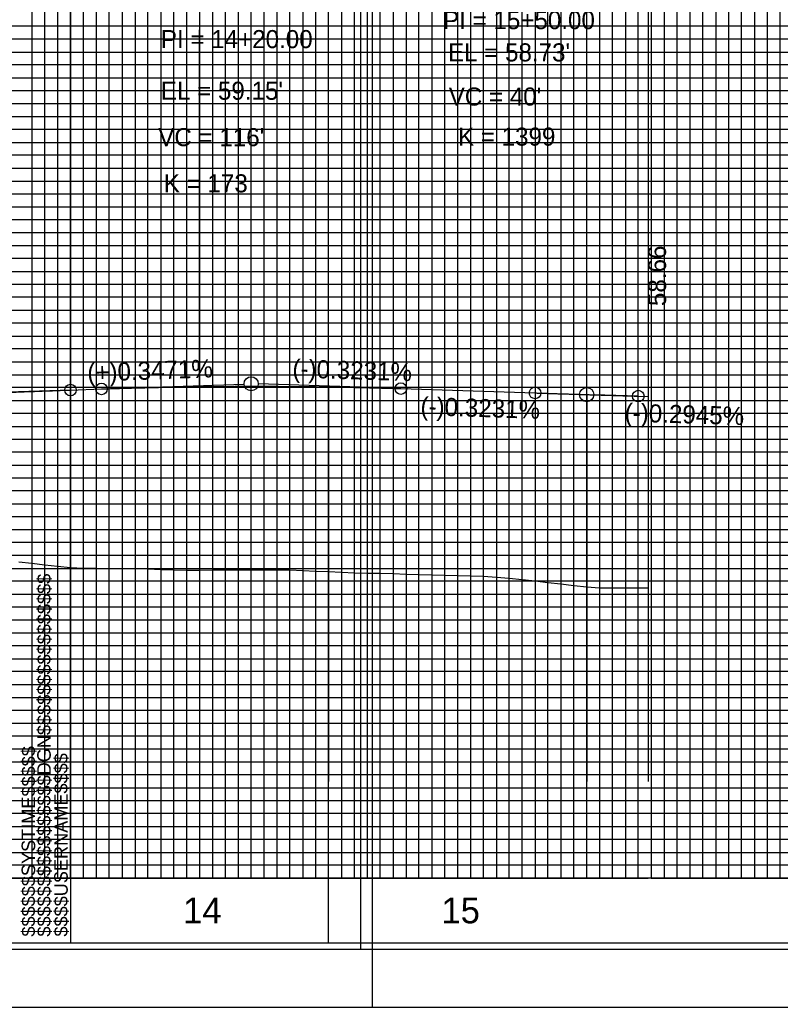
# Model space of a CAD drawing. Extents: x 2345490 to 2436403, y 465165 to 573888.
# Drawn here: x 2412225.7 to 2412520.3, y 518432.4 to 518814.9 of the extents above; entities that cross this region are included whole.
import ezdxf

# ---------------------------------------------------------------- set-up
doc = ezdxf.new("R2010")
doc.units = 0
for name, color, linetype in [('Old_Level_1', 7, 'Continuous'), ('Old_Level_18', 7, 'Continuous'), ('Old_Level_2', 7, 'Continuous'), ('Old_Level_40', 7, 'Continuous'), ('Old_Level_41', 7, 'Continuous'), ('Old_Level_42', 7, 'Continuous'), ('Old_Level_43', 7, 'Continuous'), ('Old_Level_50', 7, 'Continuous'), ('Old_Level_51', 7, 'Continuous'), ('Old_Level_63', 7, 'Continuous')]:
    doc.layers.add(name, color=color, linetype=linetype)

msp = doc.modelspace()

# ---------------------------------------------------------------- linework, layer by layer
at = {"layer": 'Old_Level_1'}
for points in [[(2412225.325, 518604.90725), (2412230.325, 518604.3525), (2412235.325, 518603.80575), (2412240.325, 518603.26725), (2412245.325, 518602.73625), (2412250.325, 518602.4955), (2412255.325, 518602.43975), (2412260.325, 518602.39125), (2412265.325, 518602.35), (2412270.325, 518602.31575), (2412275.325, 518602.22175), (2412280.325, 518601.9935), (2412285.325, 518601.77325), (2412290.325, 518601.71275), (2412295.325, 518601.756), (2412300.325, 518601.80375), (2412305.325, 518601.81125), (2412310.325, 518601.82475), (2412315.325, 518601.844), (2412320.325, 518601.8685), (2412325.325, 518601.89825), (2412330.325, 518601.77875), (2412335.325, 518601.56025), (2412340.325, 518601.346), (2412345.325, 518601.13575), (2412350.325, 518600.929), (2412355.325, 518600.726), (2412360.325, 518600.5605), (2412365.325, 518600.60725), (2412370.325, 518600.408), (2412375.325, 518600.09375), (2412380.325, 518599.97075), (2412385.325, 518599.84925), (2412390.325, 518599.72875), (2412395.325, 518599.60925)], [(2412395.325, 518599.60925), (2412400.325, 518599.49025), (2412405.325, 518599.3715), (2412410.325, 518599.056), (2412415.325, 518598.54475), (2412420.325, 518598.03325), (2412425.325, 518597.522), (2412430.325, 518596.94875), (2412435.325, 518596.36575), (2412440.325, 518595.78275), (2412445.325, 518595.19975), (2412450.325, 518594.8965), (2412455.325, 518594.9005), (2412460.325, 518594.8945), (2412465.325, 518594.88875), (2412469.095, 518594.88425)]]:
    msp.add_lwpolyline(points, dxfattribs=at)
at = {"layer": 'Old_Level_18'}
msp.add_line((2412245.325, 518457.40475), (2412245.325, 518457.40475), dxfattribs=at)
msp.add_line((2412245.325, 518457.40475), (2412245.325, 518457.40475), dxfattribs=at)
for points in [[(2412345.325, 519507.40475), (2410845.325, 519507.40475), (2410845.325, 518457.40475), (2412345.325, 518457.40475)], [(2413745.325, 519507.40475), (2412245.325, 519507.40475), (2412245.325, 518457.40475), (2413745.325, 518457.40475)]]:
    msp.add_lwpolyline(points, close=True, dxfattribs=at)
at = {"layer": 'Old_Level_2'}
for p, q in [((2412469.095, 518887.90475), (2412469.095, 518669.00475)), ((2412245.325, 518671.4755), (2412148.0735, 518668.10025)), ((2412245.325, 518671.4755), (2412257.325, 518671.892)), ((2412257.325, 518671.892), (2412312.57675, 518673.8095)), ((2412373.325, 518672.031), (2412318.07375, 518673.816)), ((2412373.325, 518672.031), (2412425.325, 518670.351)), ((2412425.325, 518670.351), (2412442.5765, 518669.79375)), ((2412465.325, 518669.116), (2412448.074, 518669.624)), ((2412465.325, 518669.116), (2412469.095, 518669.00475))]:
    msp.add_line(p, q, dxfattribs=at)
for centre, radius in [((2412257.325, 518671.892), 2.25), ((2412315.325, 518673.90475), 2.75), ((2412373.325, 518672.031), 2.25), ((2412245.325, 518671.4755), 2.25), ((2412425.325, 518670.351), 2.25), ((2412445.325, 518669.70475), 2.75), ((2412465.325, 518669.116), 2.25)]:
    msp.add_circle(centre, radius, dxfattribs=at)
for points in [[(2412045.325, 518659.12475), (2412049.325, 518659.478), (2412053.325, 518659.8265), (2412057.325, 518660.171), (2412061.325, 518660.511), (2412065.325, 518660.84675), (2412069.325, 518661.17825), (2412073.325, 518661.50525), (2412077.325, 518661.828), (2412081.325, 518662.1465), (2412085.325, 518662.4605), (2412089.325, 518662.77025), (2412093.325, 518663.07575), (2412097.325, 518663.37675), (2412101.325, 518663.6735), (2412105.325, 518663.966), (2412109.325, 518664.25425), (2412113.325, 518664.538), (2412117.325, 518664.8175), (2412121.325, 518665.0925), (2412125.325, 518665.36325), (2412129.325, 518665.62975), (2412133.325, 518665.892), (2412137.325, 518666.14975), (2412141.325, 518666.40325), (2412145.325, 518666.6525), (2412149.325, 518666.89725), (2412153.325, 518667.138), (2412157.325, 518667.374), (2412161.325, 518667.606), (2412165.325, 518667.8335), (2412169.325, 518668.05675), (2412173.325, 518668.2755), (2412177.325, 518668.49025), (2412181.325, 518668.70025), (2412185.325, 518668.90625), (2412189.325, 518669.10775), (2412193.325, 518669.305), (2412197.325, 518669.498), (2412201.325, 518669.6865), (2412205.325, 518669.87075), (2412209.325, 518670.05075), (2412213.325, 518670.2265), (2412217.325, 518670.39775), (2412221.325, 518670.56475), (2412225.325, 518670.72725), (2412229.325, 518670.8855), (2412233.325, 518671.0395), (2412237.325, 518671.18925), (2412241.325, 518671.3345), (2412245.325, 518671.4755)], [(2412257.325, 518671.892), (2412259.645, 518671.971), (2412261.965, 518672.04675), (2412264.285, 518672.1195), (2412266.605, 518672.18925), (2412268.925, 518672.25575), (2412271.245, 518672.319), (2412273.565, 518672.3795), (2412275.885, 518672.4365), (2412278.205, 518672.49075), (2412280.525, 518672.54175), (2412282.845, 518672.5895), (2412285.165, 518672.63425), (2412287.485, 518672.676), (2412289.805, 518672.7145), (2412292.125, 518672.75), (2412294.445, 518672.78225), (2412296.765, 518672.8115), (2412299.085, 518672.8375), (2412301.405, 518672.8605), (2412303.725, 518672.8805), (2412306.045, 518672.89725), (2412308.365, 518672.91075), (2412310.685, 518672.9215), (2412313.005, 518672.92875), (2412315.325, 518672.93325), (2412317.645, 518672.9345), (2412319.965, 518672.9325), (2412322.285, 518672.9275), (2412324.605, 518672.9195), (2412326.925, 518672.90825), (2412329.245, 518672.894), (2412331.565, 518672.8765), (2412333.885, 518672.856), (2412336.205, 518672.83225), (2412338.525, 518672.8055), (2412340.845, 518672.77575), (2412343.165, 518672.74275), (2412345.485, 518672.7065), (2412347.805, 518672.6675), (2412350.125, 518672.625), (2412352.445, 518672.57975), (2412354.765, 518672.53125), (2412357.085, 518672.4795), (2412359.405, 518672.42475), (2412361.725, 518672.367), (2412364.045, 518672.306), (2412366.365, 518672.242), (2412368.685, 518672.17475), (2412371.005, 518672.1045), (2412373.325, 518672.031)], [(2412425.325, 518670.351), (2412426.125, 518670.32525), (2412426.925, 518670.2995), (2412427.725, 518670.27375), (2412428.525, 518670.248), (2412429.325, 518670.22225), (2412430.125, 518670.19675), (2412430.925, 518670.17125), (2412431.725, 518670.14575), (2412432.525, 518670.12025), (2412433.325, 518670.09475), (2412434.125, 518670.0695), (2412434.925, 518670.04425), (2412435.725, 518670.019), (2412436.525, 518669.99375), (2412437.325, 518669.9685), (2412438.125, 518669.94325), (2412438.925, 518669.91825), (2412439.725, 518669.89325), (2412440.525, 518669.86825), (2412441.325, 518669.84325), (2412442.125, 518669.81825), (2412442.925, 518669.7935), (2412443.725, 518669.76875), (2412444.525, 518669.744), (2412445.325, 518669.71925), (2412446.125, 518669.6945), (2412446.925, 518669.66975), (2412447.725, 518669.64525), (2412448.525, 518669.62075), (2412449.325, 518669.59625), (2412450.125, 518669.57175), (2412450.925, 518669.54725), (2412451.725, 518669.523), (2412452.525, 518669.49875), (2412453.325, 518669.4745), (2412454.125, 518669.45025), (2412454.925, 518669.426), (2412455.725, 518669.402), (2412456.525, 518669.37775), (2412457.325, 518669.35375), (2412458.125, 518669.32975), (2412458.925, 518669.30575), (2412459.725, 518669.282), (2412460.525, 518669.258), (2412461.325, 518669.23425), (2412462.125, 518669.2105), (2412462.925, 518669.18675), (2412463.725, 518669.163), (2412464.525, 518669.1395), (2412465.325, 518669.116)]]:
    msp.add_spline(points, degree=3, dxfattribs=at)
at = {"layer": 'Old_Level_40'}
msp.add_line((2412245.325, 518457.40475), (2412245.325, 518457.40475), dxfattribs=at)
msp.add_line((2412245.325, 518457.40475), (2412245.325, 518457.40475), dxfattribs=at)
msp.add_line((2412245.325, 518457.40475), (2412245.325, 518457.40475), dxfattribs=at)
msp.add_line((2412245.325, 518457.40475), (2412245.325, 518457.40475), dxfattribs=at)
at = {"layer": 'Old_Level_41'}
for p, q in [((2412345.325, 518482.40475), (2410845.325, 518482.40475)), ((2413745.325, 518482.40475), (2412245.325, 518482.40475))]:
    msp.add_line(p, q, dxfattribs=at)
for points in [[(2412245.325, 519507.40475), (2412295.325, 519507.40475), (2412295.325, 518482.40475), (2412345.325, 518482.40475), (2412345.325, 519507.40475), (2412395.325, 519507.40475), (2412395.325, 518482.40475), (2412445.325, 518482.40475), (2412445.325, 519507.40475), (2412495.325, 519507.40475), (2412495.325, 518482.40475), (2412545.325, 518482.40475), (2412545.325, 519507.40475), (2412595.325, 519507.40475), (2412595.325, 518482.40475), (2412645.325, 518482.40475), (2412645.325, 519507.40475), (2412695.325, 519507.40475), (2412695.325, 518482.40475), (2412745.325, 518482.40475), (2412745.325, 519507.40475), (2412795.325, 519507.40475), (2412795.325, 518482.40475), (2412845.325, 518482.40475)], [(2412320.325, 518482.40475), (2412320.325, 519507.40475), (2412370.325, 519507.40475), (2412370.325, 518482.40475), (2412420.325, 518482.40475), (2412420.325, 519507.40475), (2412470.325, 519507.40475), (2412470.325, 518482.40475), (2412520.325, 518482.40475), (2412520.325, 519507.40475), (2412570.325, 519507.40475), (2412570.325, 518482.40475), (2412620.325, 518482.40475), (2412620.325, 519507.40475), (2412670.325, 519507.40475), (2412670.325, 518482.40475), (2412720.325, 518482.40475), (2412720.325, 519507.40475), (2412770.325, 519507.40475), (2412770.325, 518482.40475), (2412820.325, 518482.40475), (2412820.325, 519507.40475), (2412870.325, 519507.40475)], [(2412270.325, 519369.85475), (2412270.325, 518482.40475)], [(2412345.325, 518807.40475), (2410845.325, 518807.40475), (2410845.325, 518757.40475), (2412345.325, 518757.40475)], [(2413745.325, 518807.40475), (2412245.325, 518807.40475), (2412245.325, 518757.40475), (2413745.325, 518757.40475)], [(2412345.325, 518732.40475), (2410845.325, 518732.40475), (2410845.325, 518782.40475), (2412345.325, 518782.40475)], [(2413745.325, 518732.40475), (2412245.325, 518732.40475), (2412245.325, 518782.40475), (2413745.325, 518782.40475)], [(2412345.325, 518707.40475), (2410845.325, 518707.40475), (2410845.325, 518657.40475), (2412345.325, 518657.40475)], [(2413745.325, 518707.40475), (2412245.325, 518707.40475), (2412245.325, 518657.40475), (2413745.325, 518657.40475)], [(2412345.325, 518607.40475), (2410845.325, 518607.40475), (2410845.325, 518557.40475), (2412345.325, 518557.40475)], [(2413745.325, 518607.40475), (2412245.325, 518607.40475), (2412245.325, 518557.40475), (2413745.325, 518557.40475)], [(2412345.325, 518532.40475), (2410845.325, 518532.40475), (2410845.325, 518582.40475), (2412345.325, 518582.40475)], [(2413745.325, 518532.40475), (2412245.325, 518532.40475), (2412245.325, 518582.40475), (2413745.325, 518582.40475)], [(2412345.325, 518507.40475), (2410845.325, 518507.40475)], [(2413745.325, 518507.40475), (2412245.325, 518507.40475)], [(2412282.825, 518457.40475), (2412282.825, 518457.40475)]]:
    msp.add_lwpolyline(points, dxfattribs=at)
at = {"layer": 'Old_Level_42'}
for points in [[(2412195.325, 519369.85475), (2412195.325, 518482.40475), (2412245.325, 518482.40475), (2412245.325, 519369.85475)], [(2412295.325, 519369.85475), (2412295.325, 518482.40475), (2412345.325, 518482.40475)], [(2412345.325, 518632.40475), (2410845.325, 518632.40475), (2410845.325, 518682.40475), (2412345.325, 518682.40475)], [(2413745.325, 518632.40475), (2412245.325, 518632.40475), (2412245.325, 518682.40475), (2413745.325, 518682.40475)]]:
    msp.add_lwpolyline(points, dxfattribs=at)
at = {"layer": 'Old_Level_43'}
for points in [[(2412300.325, 519507.40475), (2412300.325, 518482.40475), (2412305.325, 518482.40475), (2412305.325, 519507.40475)], [(2412310.325, 519507.40475), (2412310.325, 518482.40475), (2412315.325, 518482.40475), (2412315.325, 519507.40475)], [(2412325.325, 519507.40475), (2412325.325, 518482.40475), (2412330.325, 518482.40475), (2412330.325, 519507.40475)], [(2412335.325, 519507.40475), (2412335.325, 518482.40475), (2412340.325, 518482.40475), (2412340.325, 519507.40475)], [(2412350.325, 519507.40475), (2412350.325, 518482.40475), (2412355.325, 518482.40475), (2412355.325, 519507.40475)], [(2412360.325, 519507.40475), (2412360.325, 518482.40475), (2412365.325, 518482.40475), (2412365.325, 519507.40475)], [(2412375.325, 519507.40475), (2412375.325, 518482.40475), (2412380.325, 518482.40475), (2412380.325, 519507.40475)], [(2412385.325, 519507.40475), (2412385.325, 518482.40475), (2412390.325, 518482.40475), (2412390.325, 519507.40475)], [(2412400.325, 519507.40475), (2412400.325, 518482.40475), (2412405.325, 518482.40475), (2412405.325, 519507.40475)], [(2412410.325, 519507.40475), (2412410.325, 518482.40475), (2412415.325, 518482.40475), (2412415.325, 519507.40475)], [(2412425.325, 519507.40475), (2412425.325, 518482.40475), (2412430.325, 518482.40475), (2412430.325, 519507.40475)], [(2412435.325, 519507.40475), (2412435.325, 518482.40475), (2412440.325, 518482.40475), (2412440.325, 519507.40475)], [(2412450.325, 519507.40475), (2412450.325, 518482.40475), (2412455.325, 518482.40475), (2412455.325, 519507.40475)], [(2412460.325, 518482.40475), (2412465.325, 518482.40475), (2412465.325, 519507.40475)], [(2412460.325, 519507.40475), (2412460.325, 518482.40475)], [(2412475.325, 519507.40475), (2412475.325, 518482.40475), (2412480.325, 518482.40475), (2412480.325, 519507.40475)], [(2412485.325, 519507.40475), (2412485.325, 518482.40475), (2412490.325, 518482.40475), (2412490.325, 519507.40475)], [(2412500.325, 519507.40475), (2412500.325, 518482.40475), (2412505.325, 518482.40475), (2412505.325, 519507.40475)], [(2412510.325, 519507.40475), (2412510.325, 518482.40475), (2412515.325, 518482.40475), (2412515.325, 519507.40475)], [(2412230.325, 519369.85475), (2412230.325, 518482.40475)], [(2412230.325, 518482.40475), (2412235.325, 518482.40475), (2412235.325, 519369.85475)], [(2412240.325, 519369.85475), (2412240.325, 518482.40475), (2412250.325, 518482.40475), (2412250.325, 519369.85475)], [(2412255.325, 519369.85475), (2412255.325, 518482.40475), (2412260.325, 518482.40475), (2412260.325, 519369.85475)], [(2412265.325, 519369.85475), (2412265.325, 518482.40475), (2412275.325, 518482.40475), (2412275.325, 519369.85475)], [(2412280.325, 519369.85475), (2412280.325, 518482.40475), (2412285.325, 518482.40475), (2412285.325, 519369.85475)], [(2412290.325, 519369.85475), (2412290.325, 518482.40475), (2412300.325, 518482.40475)], [(2412295.325, 518812.40475), (2410895.325, 518812.40475), (2410895.325, 518802.40475), (2412295.325, 518802.40475)], [(2413695.325, 518812.40475), (2412295.325, 518812.40475), (2412295.325, 518802.40475), (2413695.325, 518802.40475)], [(2412295.325, 518797.40475), (2410895.325, 518797.40475), (2410895.325, 518792.40475), (2412295.325, 518792.40475)], [(2413695.325, 518797.40475), (2412295.325, 518797.40475), (2412295.325, 518792.40475), (2413695.325, 518792.40475)], [(2412295.325, 518787.40475), (2410895.325, 518787.40475), (2410895.325, 518777.40475), (2412295.325, 518777.40475)], [(2413695.325, 518787.40475), (2412295.325, 518787.40475), (2412295.325, 518777.40475), (2413695.325, 518777.40475)], [(2412295.325, 518772.40475), (2410895.325, 518772.40475), (2410895.325, 518767.40475), (2412295.325, 518767.40475)], [(2413695.325, 518772.40475), (2412295.325, 518772.40475), (2412295.325, 518767.40475), (2413695.325, 518767.40475)], [(2412295.325, 518762.40475), (2410895.325, 518762.40475), (2410895.325, 518752.40475), (2412295.325, 518752.40475)], [(2413695.325, 518762.40475), (2412295.325, 518762.40475), (2412295.325, 518752.40475), (2413695.325, 518752.40475)], [(2412295.325, 518747.40475), (2410895.325, 518747.40475), (2410895.325, 518742.40475), (2412295.325, 518742.40475)], [(2413695.325, 518747.40475), (2412295.325, 518747.40475), (2412295.325, 518742.40475), (2413695.325, 518742.40475)], [(2412295.325, 518737.40475), (2410895.325, 518737.40475), (2410895.325, 518727.40475), (2412295.325, 518727.40475)], [(2413695.325, 518737.40475), (2412295.325, 518737.40475), (2412295.325, 518727.40475), (2413695.325, 518727.40475)], [(2412295.325, 518722.40475), (2410895.325, 518722.40475), (2410895.325, 518717.40475), (2412295.325, 518717.40475)], [(2413695.325, 518722.40475), (2412295.325, 518722.40475), (2412295.325, 518717.40475), (2413695.325, 518717.40475)], [(2412295.325, 518712.40475), (2410895.325, 518712.40475), (2410895.325, 518702.40475), (2412295.325, 518702.40475)], [(2413695.325, 518712.40475), (2412295.325, 518712.40475), (2412295.325, 518702.40475), (2413695.325, 518702.40475)], [(2412295.325, 518697.40475), (2410895.325, 518697.40475), (2410895.325, 518692.40475), (2412295.325, 518692.40475)], [(2413695.325, 518697.40475), (2412295.325, 518697.40475), (2412295.325, 518692.40475), (2413695.325, 518692.40475)], [(2412295.325, 518687.40475), (2410895.325, 518687.40475)], [(2413695.325, 518687.40475), (2412295.325, 518687.40475)], [(2410895.325, 518677.40475), (2412295.325, 518677.40475)], [(2412295.325, 518677.40475), (2413695.325, 518677.40475)], [(2412295.325, 518672.40475), (2410895.325, 518672.40475), (2410895.325, 518667.40475), (2412295.325, 518667.40475)], [(2413695.325, 518672.40475), (2412295.325, 518672.40475), (2412295.325, 518667.40475), (2413695.325, 518667.40475)], [(2412295.325, 518662.40475), (2410895.325, 518662.40475)], [(2413695.325, 518662.40475), (2412295.325, 518662.40475)], [(2410895.325, 518652.40475), (2412295.325, 518652.40475)], [(2412295.325, 518652.40475), (2413695.325, 518652.40475)], [(2412295.325, 518647.40475), (2410895.325, 518647.40475), (2410895.325, 518642.40475), (2412295.325, 518642.40475)], [(2413695.325, 518647.40475), (2412295.325, 518647.40475), (2412295.325, 518642.40475), (2413695.325, 518642.40475)], [(2412295.325, 518637.40475), (2410895.325, 518637.40475), (2410895.325, 518627.40475), (2412295.325, 518627.40475)], [(2413695.325, 518637.40475), (2412295.325, 518637.40475), (2412295.325, 518627.40475), (2413695.325, 518627.40475)], [(2412295.325, 518622.40475), (2410895.325, 518622.40475), (2410895.325, 518617.40475), (2412295.325, 518617.40475)], [(2413695.325, 518622.40475), (2412295.325, 518622.40475), (2412295.325, 518617.40475), (2413695.325, 518617.40475)], [(2412295.325, 518612.40475), (2410895.325, 518612.40475), (2410895.325, 518602.40475), (2412295.325, 518602.40475)], [(2413695.325, 518612.40475), (2412295.325, 518612.40475), (2412295.325, 518602.40475), (2413695.325, 518602.40475)], [(2412295.325, 518597.40475), (2410895.325, 518597.40475), (2410895.325, 518592.40475), (2412295.325, 518592.40475)], [(2413695.325, 518597.40475), (2412295.325, 518597.40475), (2412295.325, 518592.40475), (2413695.325, 518592.40475)], [(2412295.325, 518587.40475), (2410895.325, 518587.40475), (2410895.325, 518577.40475), (2412295.325, 518577.40475)], [(2413695.325, 518587.40475), (2412295.325, 518587.40475), (2412295.325, 518577.40475), (2413695.325, 518577.40475)], [(2412295.325, 518572.40475), (2410895.325, 518572.40475), (2410895.325, 518567.40475), (2412295.325, 518567.40475)], [(2413695.325, 518572.40475), (2412295.325, 518572.40475), (2412295.325, 518567.40475), (2413695.325, 518567.40475)], [(2412295.325, 518562.40475), (2410895.325, 518562.40475), (2410895.325, 518552.40475), (2412295.325, 518552.40475)], [(2413695.325, 518562.40475), (2412295.325, 518562.40475), (2412295.325, 518552.40475), (2413695.325, 518552.40475)], [(2412295.325, 518547.40475), (2410895.325, 518547.40475), (2410895.325, 518542.40475), (2412295.325, 518542.40475)], [(2413695.325, 518547.40475), (2412295.325, 518547.40475), (2412295.325, 518542.40475), (2413695.325, 518542.40475)], [(2412295.325, 518537.40475), (2410895.325, 518537.40475), (2410895.325, 518527.40475), (2412295.325, 518527.40475)], [(2413695.325, 518537.40475), (2412295.325, 518537.40475), (2412295.325, 518527.40475), (2413695.325, 518527.40475)], [(2412295.325, 518522.40475), (2410895.325, 518522.40475), (2410895.325, 518517.40475), (2412295.325, 518517.40475)], [(2413695.325, 518522.40475), (2412295.325, 518522.40475), (2412295.325, 518517.40475), (2413695.325, 518517.40475)], [(2412295.325, 518512.40475), (2410895.325, 518512.40475), (2410895.325, 518502.40475), (2412295.325, 518502.40475)], [(2413695.325, 518512.40475), (2412295.325, 518512.40475), (2412295.325, 518502.40475), (2413695.325, 518502.40475)], [(2412295.325, 518497.40475), (2410895.325, 518497.40475), (2410895.325, 518492.40475), (2412295.325, 518492.40475)], [(2413695.325, 518497.40475), (2412295.325, 518497.40475), (2412295.325, 518492.40475), (2413695.325, 518492.40475)], [(2412295.325, 518487.40475), (2410895.325, 518487.40475)], [(2413695.325, 518487.40475), (2412295.325, 518487.40475)]]:
    msp.add_lwpolyline(points, dxfattribs=at)
at = {"layer": 'Old_Level_50'}
for points in [[(2412357.825, 519509.95475), (2410691.325, 519509.95475), (2410691.325, 518454.85475), (2412357.825, 518454.85475)], [(2413757.825, 519509.95475), (2412091.325, 519509.95475), (2412091.325, 518454.85475), (2413757.825, 518454.85475)]]:
    msp.add_lwpolyline(points, close=True, dxfattribs=at)
at = {"layer": 'Old_Level_51'}
for points in [[(2412362.325, 519532.40475), (2410678.325, 519532.40475), (2410678.325, 518432.40475), (2412362.325, 518432.40475)], [(2413762.325, 519532.40475), (2412078.325, 519532.40475), (2412078.325, 518432.40475), (2413762.325, 518432.40475)]]:
    msp.add_lwpolyline(points, close=True, dxfattribs=at)
at = {"layer": 'Old_Level_63'}
for p, q in [((2412245.325, 518673.64475), (2412245.325, 518810.97)), ((2412295.325, 518673.02475), (2412295.325, 518810.97)), ((2412245.325, 518670.59475), (2412245.325, 518519.8805)), ((2412295.325, 518672.62475), (2412295.325, 518519.8805)), ((2412345.325, 518672.70475), (2412345.325, 518519.8805)), ((2412395.325, 518671.32475), (2412395.325, 518519.8805)), ((2412445.325, 518669.72475), (2412445.325, 518519.8805)), ((2412469.095, 518669.00475), (2412469.095, 518519.8805)), ((2410895.325, 518482.40475), (2412469.0995, 518482.40475))]:
    msp.add_line(p, q, dxfattribs=at)

# ---------------------------------------------------------------- texts
at = {"layer": 'Old_Level_1'}
for s, p in [('14', (2412288.9735, 518464.90475)), ('15', (2412389.066, 518464.90475))]:
    msp.add_text(s, height=10.000001, dxfattribs=at).set_placement(p)
at = {"layer": 'Old_Level_2'}
for s, height, p in [('PI = 15+50.00', 7.0000005, (2412389.6875, 518811.26)), ('PI = 14+20.00', 7.0000005, (2412280.325, 518803.90475)), ("EL = 58.73'", 7.0000005, (2412391.56375, 518798.76675)), ("EL = 59.15'", 7.0000005, (2412280.325, 518783.90475)), ("VC = 40'", 7.000001, (2412391.8555, 518781.65475)), ("VC = 116'", 7.000001, (2412279.31825, 518765.93775)), ('K = 1399', 7.000001, (2412395.46325, 518766.1345)), ('K = 173', 7.000001, (2412281.48275, 518748.03525))]:
    msp.add_text(s, height=height, dxfattribs=at).set_placement(p)
for s, rotation, p in [('58.66', 90, (2412476.095, 518704.00475)), ('(+)0.3471%', 1.9877028, (2412251.94875, 518674.70725)), ('(-)0.3231%', 358.14955, (2412331.22225, 518676.393)), ('(-)0.3231%', 358.14955, (2412380.84425, 518661.783)), ('(-)0.2945%', 358.3131917, (2412459.95, 518659.27))]:
    msp.add_text(s, height=7.000001, rotation=rotation, dxfattribs=at).set_placement(p)
at = {"layer": 'Old_Level_41'}
for s, p in [('$$$$$$$$$$$$$$$$DGN$$$$$$$$$$$$$$$$', (2412237.675, 518459.76725)), ('$$$$$$SYSTIME$$$$$', (2412231.625, 518459.76725)), ('$$$$USERNAME$$$$', (2412244.25, 518459.77975))]:
    msp.add_text(s, height=5.25, rotation=90, dxfattribs=at).set_placement(p)

doc.saveas('drawing.dxf')
